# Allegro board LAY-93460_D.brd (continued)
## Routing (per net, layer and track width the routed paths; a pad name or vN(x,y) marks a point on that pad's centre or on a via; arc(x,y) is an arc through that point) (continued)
P3V3_BATT: length 17.4
  TOP w0.254: 38.67,43.76 D2.A ; D2.A 39.33,44.58 ; D2.A 38.67,45.41 ; D2.A 38.01,44.58
  BOTTOM w0.254: 37.33,38.87 BT2.1 ; BT2.1 35.31,40.58 ; BT2.1 37.33,42.3 ; BT2.1 39.35,40.58 ; v2(37.33,44.58) 39.3,44.58 ; v2(37.33,44.58) 37.33,46.09 ; v2(37.33,44.58) 37.33,43.07 ; v2(37.33,44.58) 35.36,44.58
  vias: v2(37.33,45.22) v2(37.33,43.95)
P3V3_LDO: length 1.8
  TOP w0.381: SH19.2 D1.C
P5V: length 79.5
  TOP w0.381: v2(21.64,49.4) D4.C 26.33,49.4 27.5,50.57 TP7.1 C23.1 v2(31.31,52.67)
  L4_INT_2 w0.381: v2(21.64,49.4) 20.48,48.24 20.48,41.71 v2(18.74,39.97) ; v2(31.31,52.67) 33.37,52.67 34.61,51.43 v2(34.61,49.67)
  BOTTOM w0.381: v2(21.64,49.4) 22.8,49.4 23.55,48.65 23.55,44.81 23.02,44.28 23.02,39.09 23.42,38.69 24.84,38.69 25.51,38.02 25.51,36.1 24.71,35.3 SH14.1 21.9,34.23 22.33,33.8 26.56,33.8 27.69,32.67 27.69,26.46 26.69,25.46 23.93,25.46 23.35,26.04 21.27,26.04 19.43,24.2 13.37,24.2 v2(12.79,24.78)
P5V_CAN: length 112.6
  TOP w0.254: U18.2 22.99,43.18 ; U18.2 20.34,43.18 ; U18.2 21.66,42.37 ; U18.2 21.66,43.99 ; v2(15.91,40.98) U17.1 ; 27.87,41.1 v2(27.87,43.18) ; v2(27.87,43.18) 27.87,45.26 ; v2(27.87,43.18) 26.54,43.18 ; v2(27.87,43.18) 29.19,43.18 ; U20.1 v2(15.91,44.03) ; U22.1 v2(13.29,28.23) ; U24.1 v2(16.34,28.23)
  L3_INT_1 w0.381: v2(10.21,29.64) 9.29,28.72 9.29,21.02 8.42,20.15 3.99,20.15 3.26,20.88 3.26,31.37 3.72,31.83 3.72,39.82 JS4.1 5.32,40.37 6.08,39.61 8.04,39.61 8.81,40.38 v2(13.66,40.38) 14.27,40.98 v2(15.91,40.98) 17.28,42.35 17.8,42.35 18.62,43.18 v2(27.87,43.18)
  L4_INT_2 w0.381: v2(21.64,52.45) 19.94,50.75 17.65,50.75 15.91,49.01 v2(15.91,44.03) v2(15.91,40.98)
  BOTTOM w0.381: JS4.1 6.03,40.73 C106.1 U19.5 ; U23.5 v2(10.21,29.64) 10.21,28.61 10.59,28.23 v2(13.29,28.23) v2(16.34,28.23) 19.12,28.23 19.57,28.68 19.57,30.53 19.18,30.91 v2(18.87,30.91) U23.3
P12V: length 26
  L4_INT_2 w0.381: J10.3 0.75,47.5 0.75,38.35 J11.3
  BOTTOM w0.254: J9.1 9.98,48.07 ; J9.1 10.92,46.13 ; J9.1 9.98,44.19 ; J9.1 9.04,46.13 ; 21.66,45.77 D8.A ; D8.A 20.84,46.6 ; D8.A 22.49,46.6 ; D8.A 21.66,47.43 ; 0.98,48.77 J10.3 ; J10.3 2.02,49.81 ; J10.3 3.06,48.77 ; J10.3 2.02,47.72
P12V_VBAT: length 2.9
  BOTTOM w0.508: D8.C C107.1 v2(21.66,40.88)
VBAT: length 10.5
  TOP w0.381: D2.C C25.1 41.72,47.64 42.43,48.34 42.43,49.36 43.18,50.11 45.85,50.11 46.23,50.49 JP2.1
VBAT_DCDC/VBAT_PMU: length 12.2
  TOP w0.254: L7.2 40.75,42.73 ; L7.2 41.46,42.15 ; L7.2 40.03,42.15 ; U6.51 42.17,35.77 ; U6.51 41.81,36.72 ; U6.51 41.81,34.83 ; 42.65,34 U6.50 ; C68.1 42.79,41.13 ; C68.1 C69.1 ; C68.1 42.13,40.35 ; C72.1 C69.1 ; C72.1 42.79,36.89 ; C72.1 42.13,37.68 ; C69.1 42.26,38.95 ; 42.65,33.5 U6.49
VBUS_USB: length 13.4
  TOP w0.381: J3.A4 J3.B9 4.36,27.78 3.98,27.4 3.98,23.91 4.36,23.53 J3.B4 J3.A9
  BOTTOM w0.305: J3.A9 7.26,23.53 7.77,23.02 L8.1 U9.6
VCC_IF_LINK: length 119.3
  TOP w0.254: U15.5 v1(32.47,39.69)
  TOP w0.381: SW4.1 54,3.8 v2(53.69,3.49) ; v1(49.61,1.46) 43.14,1.46 42.51,2.09 J5.1 C91.1 v2(40.73,4.8)
  L3_INT_1 w0.381: v2(68.93,3.49) 67.77,4.64 v1(66.25,4.64) 65.53,5.36 v2(63.37,5.36) 62.29,4.28 59.05,4.28 v2(58.26,3.49) v2(53.69,3.49)
  L4_INT_2 w0.381: JP18.2 46.23,41.79 44.22,39.78 v2(44.22,16.42) 44.22,8.44 42.77,7 40.62,7 40,6.39 40,5.53 v2(40.73,4.8)
  BOTTOM w0.254: v2(63.37,5.36) 63.9,5.36 ; v2(63.37,5.36) 62.83,5.36 ; v2(63.37,5.36) 63.37,5.89
  BOTTOM w0.381: JP18.2 44.7,50.11 37.61,50.11 36.04,48.54 32.12,48.54 31.39,47.81 31.39,40.08 31.78,39.69 v1(32.47,39.69) ; v1(66.25,4.64) U13.6 66.25,2.84 C90.1 ; v1(49.61,1.46) 49.61,1.46 49.65,1.49 49.65,2.09 50.03,2.47 C88.1 51.01,2.84 U12.6 51.01,4.22 51.26,4.47 53.43,4.47 53.69,4.22 v2(53.69,3.49) 54.2,3.49 C93.1 55.58,2.84 U14.6
VCC_TGMCU: length 73.3
  TOP w0.203: U16.10 v1(39.26,13.47) ; U16.1 35.35,11.18 v2(35.1,10.92) ; v2(40.15,10.21) U16.7 39.26,9.09 R101.1 ; U16.15 v1(36.76,13.47)
  TOP w0.381: R67.2 55.08,18.88 v2(55.45,18.51) ; JP18.1 47.33,47.69 v2(47.33,46.17)
  L3_INT_1 w0.305: v1(36.76,13.47) v1(39.26,13.47)
  L3_INT_1 w0.381: v1(39.48,18.85) 41.05,20.42 46.82,20.42 v2(47.62,21.22) 48.25,21.86 49.26,21.86 50.81,20.3 52.39,20.3 54.19,18.51 v2(55.45,18.51)
  L4_INT_2 w0.305: v1(36.76,13.47) 36.76,11.93 35.76,10.92 v2(35.1,10.92) ; v1(39.48,18.85) 39.48,13.68 v1(39.26,13.47) 39.26,11.1 v2(40.15,10.21)
  BOTTOM w0.203: v2(55.45,18.51) U11.14
  BOTTOM w0.381: v2(47.33,46.17) 48.07,46.17 49.22,45.03 49.22,41.54 47.62,39.94 v2(47.62,21.22)
VDD_ANA: length 10.4
  TOP w0.203: v2(64.84,24.64) 64.48,25 U1.29
  L4_INT_2 w0.381: v2(64.84,24.64) 64.84,22.07 JP9.2
VDD_CORE: length 45.3
  TOP w0.254: U1.16 58.91,20.77 C14.1 v2(58.14,18.99) ; U1.41 v1(60.91,30.05)
  TOP w0.381: TP1.1 64.16,36.72 63.48,36.05 v1(62.11,36.05)
  L4_INT_2 w0.305: v1(62.11,36.04) 61.42,35.36 61.42,32.71 60.4,31.69 59.43,31.69 58.63,30.9 58.63,23.26 58.94,22.95 58.94,21.27 58.14,20.48 v2(58.14,18.99)
  BOTTOM w0.381: TP1.1 68.81,34.96 67.03,33.17 65.56,33.17 64.85,32.46 64.85,31.03 64.23,30.41 63.28,30.41 62.9,30.03 C17.1 C16.1 v1(60.91,30.05)
VDD_DCDC: length 109.6
  TOP w0.254: 61.41,21.1 U1.21
  TOP w0.381: 61.41,21.1 63.38,19.13 63.38,18.22 63.03,17.86 C31.1 v2(64.17,17.48)
  L3_INT_1 w0.381: v2(56.76,51.18) 53.73,51.18 49.92,47.36 v1(32.45,47.36) ; v1(31.75,10.92) 34.21,10.92 34.9,10.23 38.56,10.23 39.28,10.94 62.32,10.94 v2(63.81,12.44)
  L4_INT_2 w0.381: v2(64.17,17.48) 64.17,12.8 v2(63.81,12.44) ; v1(31.75,10.92) 31.08,11.59 31.08,41.04 32.45,42.41 v1(32.45,47.36)
  BOTTOM w0.254: v2(64.17,17.48) SH22.2
VDD_IC: length 172.5
  TOP w0.381: SH21.1 JP2.3
  L3_INT_1 w0.381: v1(31.31,53.73) 39.29,53.73 41.39,51.64 JP2.2 ; v1(72.21,13.57) 68.59,13.57 67.86,12.84 67.86,10.47 65.69,8.3 43.48,8.3 42.68,7.5 36.25,7.5 33.82,9.93 31.77,9.93 31.14,10.57 31.14,12.14 30.7,12.57 v1(25.06,12.57)
  L4_INT_2 w0.381: v2(71.75,33.21) 71.75,34.58 72.15,34.98 72.15,46.98 69.43,49.7 69.43,51.99 67.08,54.35 46.94,54.35 JP2.3 JP2.2 ; v1(72.21,13.57) 72.36,13.57 73.22,14.42 73.22,17.19 72,18.41 v2(72,22.21) ; v1(31.31,53.73) 29.2,53.73 26.58,51.11 26.58,39.21 25.08,37.72 25.08,30.09 24.7,29.71 24.7,27.3 24.21,26.81 24.21,19.49 24.32,19.38 24.32,18.97 25.06,18.22 v1(25.06,12.57)
VDD_IO_ABC: length 11.8
  TOP w0.254: v1(55.47,27) U1.4
  TOP w0.381: C32.1 55.42,29.84 v2(55.13,29.56)
  L3_INT_1 w0.254: v1(55.47,27) 52.17,27 JP8.2
  L4_INT_2 w0.254: v1(55.47,27) 54.72,27 54.09,27.63 54.09,29.16 54.48,29.56 v2(55.13,29.56)
VDD_LDO_CORE: length 8.1
  TOP w0.254: U1.15 v1(58.41,21.47)
  BOTTOM w0.254: JP4.2 53.99,20.49 C37.1 C36.1 57.37,20.49 57.78,20.08 C35.1 v1(58.41,21.47)
VDD_MEM: length 19.6
  L3_INT_1 w0.381: v1(62.71,48.64) 61.67,49.68 57.03,49.68 56.05,48.7 JS1.1
  BOTTOM w0.381: v2(67.94,47.62) 66.6,47.62 65.91,46.94 R20.1 R10.1 R19.1 R11.1 v1(62.71,48.64)
VDD_PA_2G4: length 11
  TOP w0.254: L2.1 64.37,28.5 U1.36
  TOP w0.381: TP3.1 66.03,33.31 64.89,32.17 C7.1 C18.1 L2.1
  L4_INT_2 w0.254: v2(66.36,37.88) 66.03,37.55 TP3.1
VDD_REG: length 51.4
  L3_INT_1 w0.381: JP8.1 53.54,23.92 55.37,25.75 56.5,25.75 57.09,25.16 57.09,23.01 57.58,22.52 64.85,22.52 66.88,20.49 JP7.1
  BOTTOM w0.381: JP9.1 68.44,16.46 67.9,16.46 JP7.1 ; JP8.1 49.82,23.92 49.1,24.65 49.1,31.83 52.62,35.36 JP3.2 52.62,39.04 53,39.42 57.14,39.42 JP10.3
VDD_RF: length 21.5
  TOP w0.203: U1.34 64.67,27.5 64.84,27.33 v1(65.34,27.33)
  L4_INT_2 w0.305: v1(66.91,30.74) 66.91,33.04 67.4,33.52 67.4,39.73 v2(65.98,41.14)
  BOTTOM w0.254: v1(65.34,27.33) 65.3,27.33 64.77,27.85 63.66,27.85 C40.1 63.16,27.71 63.16,28.07 63.6,28.5 64.79,28.5 65.4,29.12 65.4,30.27 65.87,30.74 v1(66.91,30.74)
VDD_SWITCH: length 9.4
  TOP w0.254: v2(54.62,28.29) C26.1 54.62,26.33 54.95,26 U1.6
  BOTTOM w0.381: v2(54.62,28.29) 53.96,28.95 53.96,31.18 54.62,31.83 JP1.1
VOUT_SYS/VDD_SYS: length 3.9
  TOP w0.254: U1.22 v1(61.91,21.47)
  BOTTOM w0.254: C38.1 C39.1 61.65,20.31 61.76,20.42 C165.1 61.76,21.33 v1(61.91,21.47)
ADC0_A15: length 2.6
  TOP w0.203: U1.18 v1(59.91,21.47)
  BOTTOM w0.127: v1(59.91,21.47) U1.18 R8.1
ADC_IN: length 91
  L3_INT_1 w0.127: v1(61.4,36.55) 61.4,36.06 60.97,35.63 60.11,35.63 59.22,36.52 54.21,36.52 52.47,34.78 33.92,34.78 33.04,33.89 31.51,33.89 30.68,34.72 26.68,34.72 26.18,34.23 14.07,34.23 13.2,33.36 13.2,32.09 11.55,30.44 v1(7.66,30.44)
  L4_INT_2 w0.127: v1(5.65,18.11) 7.38,19.84 7.38,30.16 v1(7.66,30.44)
  BOTTOM w0.127: v1(61.4,36.55) 58.6,36.55 58.31,36.26 58.31,33.4 56.99,32.08 56.99,23.17 R8.2 ; v1(5.65,18.11) SH2.2
AN: length 1.9
  BOTTOM w0.127: SH2.1 J1.1
ANT: length 2.3
  TOP w0.417: U1.35 L2.2 L3.1
ANT_RF: length 2
  TOP w0.417: L3.2 C1.1 L10.1
BOOT_CFG: length 5.4
  TOP w0.203: SW4.2 50.55,3.8 50.3,4.06 50.3,6.45 C113.1 SH20.2
CAN0_RX: length 69.9
  TOP w0.198: v1(59.77,30.84) 59.98,30.63 59.98,29.94 59.91,29.87 U1.43
  L3_INT_1 w0.143: v1(59.77,30.84) 48.48,30.84 48.31,31.01 48.31,31.02 47.93,31.4 43.79,31.4 41.87,29.48 27.38,29.48 26.65,28.75 25.66,28.75 v1(25.39,28.48) ; v2(18.74,38.96) 19.32,39.53 19.32,40.3 19.45,40.43 20.16,40.43 21.63,41.9 27.96,41.9 28.5,42.44 29.62,42.44 30.15,42.98 30.15,43.32 30.33,43.5 30.36,43.5 v1(30.43,43.57)
  L4_INT_2 w0.143: v1(30.43,43.57) 30.14,43.85 29.54,43.85 29.03,43.34 29.03,41.36 28.32,40.65 28.32,39.32 26.02,37.02 26.02,29.11 v1(25.39,28.48)
CAN0_TX: length 70.7
  TOP w0.198: v1(60.54,30.84) 60.33,30.63 60.33,29.94 60.41,29.87 U1.42
  L3_INT_1 w0.143: v1(30.43,44.5) 29.8,43.86 29.8,43.12 29.47,42.8 28.35,42.8 27.81,42.25 21.49,42.25 20.01,40.78 19.45,40.78 19.35,40.88 19.35,41.39 v2(18.74,42) ; v1(60.54,30.84) 60.01,31.37 59.51,31.37 59.34,31.2 48.63,31.2 48.07,31.76 48.07,31.76 47.96,31.76 47.95,31.76 43.75,31.76 43.75,31.76 43.64,31.76 43.53,31.65 43.53,31.65 41.72,29.83 27.23,29.83 26.5,29.1 25.69,29.1 v1(25.39,29.41)
  L4_INT_2 w0.143: v1(25.39,29.41) 25.66,29.68 25.66,37.17 27.97,39.47 27.97,40.8 28.68,41.51 28.68,43.49 29.39,44.21 30.14,44.21 v1(30.43,44.5)
CAN1_RX: length 14.1
  TOP w0.203: R117.2 12.9,23.65 19.13,23.65 JP27.3
CAN1_TX: length 9.1
  TOP w0.203: JP28.3 20.89,26.17 18.82,24.1 15.5,24.1 R120.2
CAN_DIR: length 24.2
  TOP w0.203: v2(17.72,39.97) U17.5
  TOP w0.254: U22.5 v2(12.79,25.79)
  L3_INT_1 w0.127: v1(12.14,39.11) 12.6,39.57 14.08,39.57 14.74,40.22 15.61,40.22 15.86,39.97 v2(17.72,39.97)
  L4_INT_2 w0.127: v2(12.79,25.79) 12.37,26.21 12.37,30.67 13.75,32.05 13.75,35.59 14.54,36.37 14.54,37.88 13.31,39.11 v1(12.14,39.11)
CAN_HI_1: length 19.5
  TOP w0.198: R99.2 7.63,42.03 v1(6.99,41.39)
  L4_INT_2 w0.143: v1(6.99,41.39) 8.23,42.63 8.23,47.96 7.05,49.14 5.47,49.14 4.12,50.49 4.12,51.73 3.1,52.75 2.16,52.75 2.02,52.9 J10.1
  BOTTOM w0.198: U19.7 7.25,41.65 v1(6.99,41.39)
CAN_HI_2: length 22.4
  TOP w0.198: v1(10.22,31.93) 10.67,31.93 R118.2
  L4_INT_2 w0.143: J11.1 2.02,41.21 2.16,41.07 3.98,41.07 5.49,39.56 8.84,39.56 9.65,38.74 9.65,35.98 9.98,35.65 10.99,35.65 11.9,34.73 11.9,32.65 11.18,31.93 v1(10.22,31.93)
  BOTTOM w0.198: v1(10.22,31.93) 10.47,32.18 U23.7
CAN_LO_1: length 20.1
  TOP w0.198: v1(6.99,40.63) 7.63,39.99 R45.1
  L4_INT_2 w0.143: J10.2 2.02,52.25 2.16,52.4 2.95,52.4 3.76,51.58 3.76,50.35 5.32,48.79 6.9,48.79 7.87,47.81 7.87,42.8 6.9,41.82 6.77,41.82 6.48,41.53 6.48,41.14 v1(6.99,40.63)
  BOTTOM w0.198: U19.6 7.25,40.38 v1(6.99,40.63)
CAN_LO_2: length 22.9
  TOP w0.198: R119.1 10.67,31.17 v1(10.21,31.17)
  L4_INT_2 w0.143: J11.2 2.02,40.57 2.16,40.71 3.83,40.71 5.35,39.2 8.69,39.2 9.29,38.6 9.29,35.83 9.83,35.29 10.84,35.29 11.55,34.58 11.55,32.8 11.03,32.28 10.47,32.28 10.4,32.36 10.04,32.36 9.79,32.11 9.79,31.58 v1(10.21,31.17)
  BOTTOM w0.198: U23.6 10.46,30.91 v1(10.21,31.17)
CAN_RX_1: length 2.4
  TOP w0.198: U17.3 v1(15.07,39.47)
  BOTTOM w0.198: U19.4 14.7,39.11 v1(15.07,39.47)
CAN_RX_2: length 14.9
  TOP w0.198: v1(11.78,27.54) U22.3
  L3_INT_1 w0.143: v1(11.78,27.54) 12.4,26.93 14.86,26.93 15.26,27.32 15.26,27.47 15.26,27.47 15.26,28.07 14.31,29.01 14.31,30.23 14.69,30.6 16.55,30.6 17.04,31.09 17.77,31.09 18.1,30.76 18.1,30.41 v1(18.87,29.64)
  BOTTOM w0.198: v1(18.87,29.64) U23.4
CAN_TX_1: length 2.5
  TOP w0.198: U20.3 v1(15.06,42.52)
  BOTTOM w0.198: U19.1 14.66,42.92 v1(15.06,42.52)
CAN_TX_2: length 11.6
  TOP w0.198: v1(14.83,27.54) U24.3
  L3_INT_1 w0.143: v1(18.87,32.84) 18.1,32.08 18.1,31.81 17.73,31.45 16.89,31.45 16.4,30.96 14.54,30.96 13.96,30.38 13.96,28.87 14.83,27.99 v1(14.83,27.54)
  BOTTOM w0.198: v1(18.87,32.84) 18.26,33.45 U23.1
CS: length 13.4
  TOP w0.203: TP11.1 70.26,48.89 69.75,49.4 65.81,49.4 64.03,47.62 v2(60.68,47.62)
  BOTTOM w0.203: R21.2 v2(60.68,47.62) R11.2
DBGIF_DETECT: length 1.4
  TOP w0.203: U6.78 R81.1
DBGIF_ISP0_CTRL: length 4.4
  TOP w0.203: U6.72 31.31,37.29 32.22,38.2 32.22,38.72 31.91,39.04 U15.2
DBGIF_RESET: length 49.7
  TOP w0.254: U6.90 v1(29.39,27)
  L3_INT_1 w0.127: v1(28.47,11.81) 28.51,11.76 30.22,11.76 30.56,11.42 30.56,10.33 33.81,7.07 42.86,7.07 43.66,7.87 55.81,7.87 v1(56.88,6.8)
  L4_INT_2 w0.127: v1(28.47,11.81) 28.47,14.93 29.39,15.86 v1(29.39,27)
  BOTTOM w0.203: U14.3 v1(56.88,6.8)
DBGIF_RESET_TXEN: length 59.7
  TOP w0.203: U6.71 v1(31.81,34.54)
  L3_INT_1 w0.127: v2(56.23,2.47) 49.36,2.47 48.58,1.69 40.71,1.69 40.26,2.14 35.37,2.14 34.63,1.39 v1(33.7,1.39)
  L4_INT_2 w0.127: v1(33.7,1.39) 33.7,8.2 32.93,8.96 32.93,11.14 32.3,11.77 32.3,34.05 v1(31.81,34.54)
  BOTTOM w0.203: U14.5 v2(56.23,2.47)
DBGIF_TCK_SWCLK: length 65.6
  TOP w0.203: v1(41.29,37.03) 40.65,37.03 40.31,36.69 U6.54
  L3_INT_1 w0.127: v1(61.72,1.04) 61.05,1.71 59.12,1.71 58.4,0.99 40.3,0.99 v1(39.9,1.39)
  L4_INT_2 w0.127: v1(39.9,1.39) 39.9,4.68 39.5,5.08 39.5,6.88 40.19,7.58 42.22,7.58 43.58,8.94 43.58,34.74 v1(41.29,37.03)
  BOTTOM w0.203: U10.2 v1(61.72,1.04)
DBGIF_TDI: length 47.5
  TOP w0.203: v1(33.77,18.54) 33.77,18.84 33.57,19.05 33.01,19.05 32.81,19.25 U6.7
  L3_INT_1 w0.127: v1(35.68,1.39) 36.4,0.68 58.88,0.68 59.23,1.04 v1(60.91,1.04)
  L4_INT_2 w0.127: v1(33.77,18.54) 33.77,10.08 35.11,8.74 35.11,6.57 35.68,6 v1(35.68,1.39)
  BOTTOM w0.203: v1(60.91,1.04) 61.22,1.35 U10.3
DBGIF_TDO_SWO: length 55.5
  TOP w0.203: v1(30.19,31) 29.69,30.5 U6.83
  L3_INT_1 w0.127: v1(29.56,10.79) 29.56,5.81 30.16,5.21 32.96,5.21 34.52,6.77 42.98,6.77 43.78,7.57 51.16,7.57 v1(53.23,5.5)
  L4_INT_2 w0.127: v1(30.19,31) 30.19,29.79 30.47,29.51 30.47,14.88 29.56,13.97 v1(29.56,10.79)
  BOTTOM w0.203: v1(53.23,5.5) 52.8,5.06 52.51,5.06 52.31,5.27 U12.3
DBGIF_TMS_SWDIO: length 67.4
  TOP w0.203: U6.81 28.88,31.5 v1(29.38,31)
  L3_INT_1 w0.127: v1(29.43,14.7) 29.96,14.17 35.72,14.17 36.29,14.73 45.19,14.73 46.33,13.6 52.18,13.6 53.8,11.98 61.96,11.98 64.07,14.09 v1(67.55,14.09)
  L4_INT_2 w0.127: v1(67.55,14.09) v1(67.55,6.93) ; v1(29.43,14.7) 30.17,15.44 30.17,29.3 29.38,30.08 v1(29.38,31)
  BOTTOM w0.203: v1(67.55,6.93) U13.3
DBGIF_TMS_SWDIO_TXEN: length 67.9
  TOP w0.203: v1(37.84,34.18) 37.48,34.54 34.6,34.54 34.31,34.83 U6.66
  L3_INT_1 w0.127: v1(38.53,14.14) 45.3,14.14 46.15,13.29 51.93,13.29 53.55,11.67 62.08,11.67 63.87,13.45 v1(66.9,13.45)
  L4_INT_2 w0.127: v1(66.9,13.45) v2(66.9,2.47) ; v1(37.84,34.18) 39.28,32.75 39.28,21.1 38.53,20.35 v1(38.53,14.14)
  BOTTOM w0.203: U13.5 v2(66.9,2.47)
DBGIF_VREF: length 5.3
  TOP w0.254: R43.2 R44.1 C82.1 41.42,18.49 40.81,19.1 U6.23
DCDC_LX: length 1.8
  TOP w0.279: U1.20 60.91,20.51
EXTAL32K: length 5.7
  TOP w0.127: R31.1 65.95,21.5 65.95,23.24 65.06,24.13 64.52,24.13 64.15,24.5 U1.28
EXTAL32K_PTD5: length 3.1
  TOP w0.127: R31.2 68.2,20.71 68.52,21.03 Y2.2 C50.1
EXTAL_32M: length 0.9
  TOP w0.203: Y1.3 R32.1
EXTAL_RF: length 5.4
  TOP w0.127: v1(64.41,27) U1.33
  L3_INT_1 w0.127: v1(64.41,27) 65.19,26.21 67,26.21 67.94,25.28 v2(67.94,24.92)
FL_USB1_DM: length 40.9
  TOP w0.228: U6.35 42.49,26.5 v1(42.17,26.82) ; R39.2 9.07,25.47 9.95,25.47 v1(10.24,25.19)
  BOTTOM w0.228: v1(42.17,26.82) 42.17,26.58 42.04,26.45 42.04,25.98 41.77,25.72 32.7,25.72 27.99,21.01 20.16,21.01 18.12,23.05 12.24,23.05 11.4,23.89 11.4,25.25 11.18,25.47 10.53,25.47 v1(10.24,25.19)
FL_USB1_DP: length 41.4
  TOP w0.228: U6.34 41.94,26 41.56,26.39 v1(41.56,26.82) ; v1(10.24,26.12) 9.95,25.83 9.07,25.83 R40.2
  BOTTOM w0.228: v1(10.24,26.12) 10.53,25.83 11.32,25.83 11.75,25.4 11.75,24.04 12.39,23.4 18.27,23.4 20.31,21.36 27.84,21.36 32.55,26.07 41.63,26.07 41.68,26.13 41.68,26.45 41.56,26.58 v1(41.56,26.82)
FL_USB_5V0: length 120.1
  TOP w0.381: v2(12.27,19.21) C76.1 C75.1 v2(10.24,23.02)
  L3_INT_1 w0.381: v1(48.23,50.11) 39.92,50.11 38.88,51.16 29.81,51.16 28.52,52.45 v2(23.8,52.45) 22.12,50.77 21.36,50.77 20.34,49.75 7.75,49.75 5.32,47.31 JS4.2 ; v2(12.27,19.21) 5.34,19.21 4.32,18.19 v1(3.26,18.19)
  L4_INT_2 w0.381: v2(46.22,30) 46.22,40.52 48.49,42.79 48.49,46.75 49.27,47.53 49.27,49.07 v1(48.23,50.11)
  BOTTOM w0.381: JS4.2 4.06,43.43 3.52,42.89 3.52,31.63 3.26,31.37 3.26,28.15 2.23,27.12 2.23,23.33 3.26,22.3 v1(3.26,18.19) ; v2(12.27,19.21) 12.27,21.26 13.28,22.27 v2(15.27,22.27)
GPO0: length 97
  TOP w0.203: U1.13 v1(57.41,21.47)
  L3_INT_1 w0.127: v1(59.41,34.17) 60.35,35.11 62.32,35.11 63.58,36.37 63.58,38.29 62.64,39.23 48.69,39.23 46.07,36.61 45.1,36.61 44.34,35.85 v1(27.34,35.85)
  L4_INT_2 w0.127: v1(57.41,21.47) 57.41,22.46 57.01,22.86 57.01,31.13 59.41,33.52 v1(59.41,34.17) ; J12.1 30.7,4.77 31.89,5.97 31.89,9.09 31.44,9.55 28.42,9.55 27.56,10.41 27.56,15.21 28.54,16.19 28.54,28.89 27.62,29.8 27.62,35.57 v1(27.34,35.85)
GPO1: length 97.9
  TOP w0.203: U1.14 v1(57.91,21.07)
  L3_INT_1 w0.127: v1(60.41,34.17) 60.95,34.71 62.41,34.71 63.88,36.18 63.88,38.42 62.77,39.53 48.65,39.53 45.97,36.85 45,36.85 44.31,36.16 28.96,36.16 28.79,36.32 v1(28,36.32)
  L4_INT_2 w0.127: v1(60.41,34.17) 60.41,33.31 59.78,32.69 59.1,32.69 57.42,31.01 57.42,23.06 57.91,22.57 v1(57.91,21.07) ; v1(28,36.32) 28,29.95 28.92,29.02 28.92,16.06 27.93,15.06 27.93,10.75 28.75,9.94 31.82,9.94 32.32,9.43 32.32,5.88 32.7,5.5 J12.2
GPO2: length 111.7
  TOP w0.203: U1.17 v1(59.41,21.07)
  L3_INT_1 w0.127: JP23.3 6.84,7.19 11.53,7.19 v1(12.69,8.35) ; v1(62.51,34.17) 64.19,35.84 64.19,38.55 62.89,39.84 48.53,39.84 45.79,37.09 44.9,37.09 44.27,36.46 29.48,36.46 29.17,36.78 27.37,36.78 25.78,35.19 18.53,35.19 17.48,36.24 14.21,36.24 v1(13.27,35.3)
  L4_INT_2 w0.127: v1(12.69,8.35) 12.69,10.27 12.02,10.94 12.02,14.92 11.58,15.37 11.58,15.39 11.11,15.86 11.11,30.53 13.27,32.69 v1(13.27,35.3) ; v1(62.51,34.17) 61.91,33.56 61.91,30.7 61.43,30.22 61.43,29.79 59.65,28.01 59.65,21.88 59.41,21.64 v1(59.41,21.07)
H/RST: length 1
  BOTTOM w0.203: v2(67.94,46.35) R20.2
HW_VER_1: length 3.1
  TOP w0.203: U6.73 30.81,37.48 R102.1
HW_VER_2: length 4
  TOP w0.203: U6.65 34.81,37.33 35.27,37.79 36.22,37.79 R104.1
HW_VER_3: length 2.1
  TOP w0.203: U6.1 29.81,19.02 29.55,18.76 R105.1
HW_VER_4: length 6.6
  TOP w0.203: R106.1 43,21.25 42.53,21.71 42.53,24.3 42.74,24.5 U6.31
HW_VER_6: length 41
  TOP w0.203: U6.56 v1(39.31,36.95)
  L4_INT_2 w0.127: JP21.2 41.84,43.25 39.31,40.72 v1(39.31,36.95) 39.31,34.74 41.65,32.4 41.65,29.35 40.88,28.58 40.88,24.91 41.65,24.14 v1(41.65,11.68)
  BOTTOM w0.127: v1(41.65,11.68) 41.65,12.52 42.16,13.03 Q3.1
HW_VER_7: length 44.2
  TOP w0.127: U6.27 v1(44.8,22.5)
  TOP w0.203: v1(59.28,3.49) JP22.2
  L3_INT_1 w0.127: v1(63.92,21.18) 63.35,20.61 55.7,20.61 53.4,22.91 45.21,22.91 v1(44.8,22.5)
  L4_INT_2 w0.127: JP22.2 59.28,11.78 63.16,15.66 63.16,20.42 v1(63.92,21.18)
  BOTTOM w0.203: v1(59.28,3.49) 59.97,3.49 60.72,4.24 U10.5
HW_VER_8: length 3.7
  TOP w0.203: U6.55 39.81,36.83 40.75,37.76 R96.1
I2C1_SCL: length 67.8
  TOP w0.203: U1.3 v1(55.88,27.5)
  L3_INT_1 w0.127: v1(57.24,37.88) 56.48,37.12 53.84,37.12 52.1,35.38 26.66,35.38 26.12,34.84 15.26,34.84 v2(14.79,35.3)
  L4_INT_2 w0.127: v1(55.88,27.5) 56.61,28.23 56.61,31.49 58.4,33.28 58.4,35.38 57.26,36.52 57.26,37.86 v1(57.24,37.88) 57.24,39.44 57.74,39.94 57.74,43.48 58.14,43.88 v1(58.14,44.57)
  BOTTOM w0.127: R206.2 54.66,26.98 55.17,27.5 v1(55.88,27.5)
  BOTTOM w0.203: R15.1 58.65,45.08 v1(58.14,44.57)
I2C1_SDA: length 106.7
  TOP w0.203: U1.2 v1(55.47,28)
  L3_INT_1 w0.127: v1(17.33,26.29) 20.4,26.29 22.16,24.52 25.42,24.52 26.31,25.41 47.99,25.41 50.14,27.56 55.04,27.56 v1(55.47,28) ; JP24.3 7.42,12.95 v1(14.54,12.95) ; v1(57.63,48.64) 61.5,48.64 63.15,46.99 69.34,46.99 v1(69.98,46.35)
  L4_INT_2 w0.127: v1(14.54,12.95) 14.54,15.37 16.25,17.08 16.25,19.86 16.87,20.48 16.87,25.83 v1(17.33,26.29) ; v1(55.47,28) 56.2,28.73 56.2,31.53 57.99,33.31 57.99,35.24 56.57,36.65 56.57,39.38 57.37,40.18 57.37,43.79 57.63,44.05 v1(57.63,48.64)
  BOTTOM w0.127: v1(55.47,28) 55.12,28 54.75,27.63 54.12,27.63 R205.2
  BOTTOM w0.203: R21.1 v1(57.63,48.64) ; R18.1 v1(69.98,46.35)
I2C_SCL: length 1.8
  BOTTOM w0.127: J2.5 SH11.2
I2C_SDA: length 1.8
  BOTTOM w0.127: J2.6 SH13.2
IF_DETECT: length 57.9
  TOP w0.203: R81.2 27.14,34.54 29.14,34.54 29.34,34.34 v1(29.34,34)
  L3_INT_1 w0.127: v1(28.92,10.54) 28.92,5.81 29.83,4.9 38.69,4.9 41.17,2.43 47.93,2.43 v2(49.04,3.53)
  L4_INT_2 w0.127: v1(29.34,34) 28.87,33.53 28.87,30.13 29.86,29.15 29.86,15.82 28.92,14.88 v1(28.92,10.54)
  BOTTOM w0.203: v2(49.04,3.53) J5.9 D14.C
IF_ISPEN: length 46.6
  L3_INT_1 w0.127: v1(42.16,9.29) v1(46.96,9.29)
  L4_INT_2 w0.127: v1(42.16,9.29) 42.16,10.51 41.21,11.45 41.21,24.07 40.5,24.79 40.5,28.72 41.21,29.44 41.21,32.37 36.77,36.82 36.77,37.42 36.11,38.09 36.11,38.09 v2(35.81,38.39) ; J5.7 46.96,4.17 v1(46.96,9.29)
  BOTTOM w0.203: J5.7 46.32,2.73 45.97,2.38 44.65,2.38 44.45,2.18 D13.C
IF_TCK_SWDCLK: length 34.7
  L3_INT_1 w0.127: v2(43.78,6.33) 49.81,6.33 51.55,4.59 56.23,4.59 57.29,5.66 v2(58.26,5.66)
  BOTTOM w0.203: J5.4 v2(43.78,6.33) 43.78,7.34 47.08,10.63 47.08,14.8 47.28,15.01 D15.5 48.89,15.01 50.02,16.13 52.62,16.13 53.01,16.53 U11.3
IF_TDI: length 25.6
  TOP w0.203: v1(46.46,15.66) 45.64,14.85 45.64,11.31 46.32,10.63 J5.8
  L3_INT_1 w0.127: J5.8 47.24,5.72 49.38,5.72 51.15,3.95 57.56,3.95 v2(58.26,4.64)
  BOTTOM w0.203: D15.3 v1(46.46,15.66)
IF_TDO_SWO: length 37.7
  TOP w0.203: J5.6 45.05,10.44 44.83,10.66 44.83,15.06 45.64,15.87 v1(45.64,16.42)
  L4_INT_2 w0.127: J5.6 44.43,4.18 44.43,2.45 45.41,1.47 48.94,1.47 49.44,1.98 52.15,1.98 v2(52.67,1.46)
  BOTTOM w0.203: U11.11 53.41,19.53 52.8,20.14 46.75,20.14 45.64,19.03 v1(45.64,16.42) 45.66,16.4 46.57,16.4 47.32,15.66 D15.4
IF_TMS_SWDIO: length 73.1
  TOP w0.203: J5.2 41.5,5.82 v2(40.73,5.82)
  L3_INT_1 w0.127: v1(48.63,14.36) 49.08,13.9 52.44,13.9 53.81,12.52 v1(61.29,12.52) ; v1(68.31,5.83) 62.72,5.83 61.98,5.09 57.97,5.09 57.16,4.28 51.35,4.28 49.6,6.02 44.81,6.02 44.61,5.82 v2(40.73,5.82)
  L4_INT_2 w0.127: v1(48.63,14.36) 45.29,11.02 45.29,8.61 43.02,6.34 41.25,6.34 v2(40.73,5.82) ; v2(67.91,1.46) 67.91,3.99 68.31,4.39 v1(68.31,5.83)
  BOTTOM w0.203: D15.6 v1(48.63,14.36) ; U11.15 55.01,18.11 56.08,17.04 58.6,17.04 61.29,14.36 v1(61.29,12.52)
IF_TRGRST_SWDRST: length 34.6
  TOP w0.203: J5.10 47.59,10.68 46.46,11.81 v1(46.46,14.36)
  L3_INT_1 w0.127: J5.10 49.69,4.8 51.56,2.93 56.71,2.93 57.24,2.39 v2(57.24,1.46) ; v1(50.15,19.61) 49.13,18.59 47.43,18.59 v1(46.91,19.11)
  L4_INT_2 w0.127: v1(46.91,19.11) 47.75,18.27 47.75,15.66 v1(46.46,14.36)
  BOTTOM w0.127: U11.7 51.48,18.51 50.56,18.51 50.15,18.92 v1(50.15,19.61)
  BOTTOM w0.203: v1(46.46,14.36) D15.1
L_B4: length 1.3
  TOP w0.203: R22.2 LED4.C
L_G2: length 1.3
  TOP w0.203: R23.1 LED2.C
LED1_B1: length 4.4
  TOP w0.203: JS14.2 29.1,6.33 28.42,5.65 R28.2 Q1.1
LED2_G: length 2.5
  TOP w0.203: Q2.3 R23.2
LED2_G2: length 2.3
  TOP w0.203: Q2.1 R29.2 R27.1
LED4_B: length 2.9
  TOP w0.203: Q1.3 R22.1
LED_RTS: length 1.8
  TOP w0.203: R24.2 JS3.2
LLWU/NMI_B: length 7.6
  BOTTOM w0.203: SH5.2 12,35.94 12,38.19 11.73,38.46 9.57,38.46 J2.2
LPSPI_PCS0: length 86.4
  TOP w0.203: v1(58.91,36.05) 58.41,35.55 U1.46
  L3_INT_1 w0.127: v1(14.64,33.66) 14.91,33.92 26.65,33.92 27.04,33.53 33.18,33.53 34.14,34.49 36.91,34.49 37.7,33.7 41.38,33.7 42.15,34.47 52.74,34.47 54.26,35.99 55.23,35.99 55.63,35.6 58.46,35.6 v1(58.91,36.05)
  L4_INT_2 w0.127: v1(14.64,33.66) 14.16,33.17 14.16,31.92 12.68,30.45 12.68,26.99 13.3,26.37 13.3,18.65 v1(11.74,17.09) ; v1(58.65,47.62) 58.14,47.11 58.14,45.43 58.65,44.92 58.65,40.2 59.39,39.46 59.39,36.53 v1(58.91,36.05)
  BOTTOM w0.127: SH4.2 v1(11.74,17.09)
  BOTTOM w0.203: v1(58.65,47.62) R16.1
LPSPI_SCK: length 88.8
  TOP w0.203: U1.48 v1(57.41,34.17)
  L3_INT_1 w0.127: v1(64.17,34.17) 63.47,34.17 63,33.7 57.88,33.7 v1(57.41,34.17) 42.45,34.17 41.68,33.4 37.55,33.4 36.76,34.19 34.35,34.19 33.36,33.2 26.91,33.2 26.5,33.62 15.59,33.62 v1(15.28,33.3)
  L4_INT_2 w0.127: v1(14.28,17.09) 14.28,26.53 13.91,26.9 13.91,30.48 14.83,31.4 14.83,32.86 15.27,33.3 v1(15.28,33.3)
  BOTTOM w0.127: v1(14.28,17.09) SH6.2
  BOTTOM w0.203: v1(64.17,34.17) 64.17,35.95 65.25,37.03 65.25,38.42 65.69,38.86 67.56,38.86 69.96,41.26 69.96,44.76 69.63,45.08 R12.1
LPSPI_SIN: length 72.2
  TOP w0.203: U1.47 v1(57.91,30.05)
  L3_INT_1 w0.127: v1(16.82,16.58) 19.6,16.58 24.35,21.33 v1(31.75,21.33) ; v1(57.91,30.05) 50.12,30.05 47.11,27.05 43.37,27.05 42.94,27.47 32.23,27.47 v1(31.75,26.98)
  L4_INT_2 w0.127: v1(31.75,21.33) v1(31.75,26.98) ; v1(57.91,30.05) 57.91,30.84 59.35,32.29 60.03,32.29 60.88,33.14 60.88,34.64 59.68,35.84 59.68,39.58 59.03,40.23 59.03,45.97 v1(58.65,46.35)
  BOTTOM w0.127: SH8.2 16.31,17.09 v1(16.82,16.58)
  BOTTOM w0.203: R13.1 v1(58.65,46.35)
LPSPI_SOUT: length 92.4
  TOP w0.203: U1.1 56.14,28.5 55.97,28.67 55.97,29.14 56.91,30.08 v1(56.91,33.4)
  L3_INT_1 w0.127: v1(15.91,32.94) 16.28,33.31 26.37,33.31 26.84,32.84 33.64,32.84 34.68,33.88 36.63,33.88 37.47,33.04 41.97,33.04 42.79,33.86 55.48,33.86 55.93,33.4 v1(56.91,33.4) v1(63.45,33.4)
  L4_INT_2 w0.127: v1(14.28,16.19) 14.75,16.67 14.75,26.7 14.27,27.18 14.27,30.29 15.3,31.31 15.3,32.33 v1(15.91,32.94)
  BOTTOM w0.127: SH10.2 18.35,17.53 18.22,17.66 15.16,17.66 14.9,17.4 14.9,16.43 14.66,16.19 v1(14.28,16.19)
  BOTTOM w0.203: v1(63.45,33.4) 63.45,36.24 64.44,37.23 64.44,38.83 65.14,39.52 66.87,39.52 68.96,41.61 R14.1
MCU_LINK_3V3: length 84.4
  TOP w0.254: 20.54,20.84 L4.2 21.11,20.12 ; U6.84 27.11,30 v2(26.61,30.5) ; U6.95 v2(26.61,24.5) ; v2(26.61,23.52) 26.64,23.54 26.64,23.61 27.03,24 U6.96 ; v2(45.08,30.74) 44.82,31 U6.44 ; v2(32.81,37.21) U6.69 ; 25.61,20.84 C51.1 24.82,20.17 ; v2(35.81,37.21) U6.63 ; U6.75 v2(29.81,37.21) ; U6.15 36.81,19.43 36.28,18.89 34.99,18.89 34.54,18.44 v2(34.54,17.78) ; 23.04,20.17 C54.1 ; U6.38 44.77,28 v2(45.08,27.69)
  TOP w0.381: L4.2 C54.1 C51.1
  L3_INT_1 w0.381: v1(26.61,17.78) v2(34.54,17.78) 43.17,17.78 v2(45.2,19.81) ; v2(29.81,37.21) v2(32.81,37.21) 33.07,37.21 33.11,37.17 33.56,37.17 33.6,37.21 v2(35.81,37.21)
  L4_INT_2 w0.381: v2(45.2,19.81) 45.89,20.49 45.89,23.92 45.08,24.73 v2(45.08,27.69) ; v1(26.61,17.78) v2(26.61,23.52) v2(26.61,24.5) 25.72,25.39 25.72,27.57 26.61,28.46 v2(26.61,30.5) 26.61,36.33 27.49,37.21 v2(29.81,37.21)
  BOTTOM w0.381: v2(45.08,30.74) 44.68,30.74 44.3,30.36 44.3,28.08 44.68,27.69 v2(45.08,27.69)
MCU_LINK_N_16MHZ: length 6.1
  TOP w0.203: U6.28 45.07,23 45.96,23.89 Y4.1 C78.1
MCU_LINK_P_16MHZ: length 7.3
  TOP w0.203: U6.29 44.78,23.5 45.48,24.2 45.48,25.33 46.04,25.89 Y4.2 C77.1
MCU_LINK_RST: length 58
  TOP w0.203: v1(42.07,22.5) 42.07,24.32 42.32,24.58 42.33,24.58 42.6,24.84 42.6,24.85 42.75,25 U6.32
  L3_INT_1 w0.127: J4.10 11.04,1.99 22.87,1.99 23.62,1.23 v1(23.62,1.23) ; v1(42.07,22.5) 40.31,22.5 38.26,20.44 25.86,20.44 v1(23.21,17.79)
  L4_INT_2 w0.127: v1(23.21,17.79) 23.21,16.96 24.33,15.84 24.33,8.75 21.94,6.36 21.94,3.88 23.62,2.2 v1(23.62,1.23)
MCU_LINK_USB_CC1: length 1.9
  TOP w0.381: J3.A5 6.99,26.93 R112.1
MCU_LINK_USB_CC2: length 1.2
  BOTTOM w0.305: J3.B5 R113.1
MCU_LINK_USB_DN: length 4.6
  TOP w0.203: R39.1 7.17,25.1 7.04,25.23 J3.A7
  BOTTOM w0.127: J3.A7 6.64,25.23 6.81,25.4 U9.1
  BOTTOM w0.203: J3.A7 5.62,25.71 5.12,25.71 J3.B7
MCU_LINK_USB_DP: length 4.6
  TOP w0.203: R40.1 7.17,26.2 7.04,26.08 J3.A6 5.62,25.59 5.12,25.59 J3.B6
  BOTTOM w0.127: J3.A6 6.64,26.08 6.81,25.9 U9.2
MCU_LNK_RX: length 27
  TOP w0.203: v1(36.39,33.41) 35.64,34.16 32.81,34.16 32.31,34.66 U6.70 ; v1(37.76,14.14) U16.13
  L4_INT_2 w0.127: v1(37.76,14.14) 37.76,20.24 37.33,20.67 37.33,32.47 v1(36.39,33.41)
MCU_LNK_TX: length 28.7
  TOP w0.203: U16.14 37.26,13.64 v1(36.76,14.14) ; v1(35.32,32.86) 32.86,32.86 32.5,32.5 U6.79
  L4_INT_2 w0.127: v1(35.32,32.86) 35.73,32.86 36.31,32.28 36.31,14.59 v1(36.76,14.14)
MCULINK_VDDA: length 6.6
  TOP w0.254: U6.16 C64.1 C63.1 37.31,15.66 37.44,15.54 R33.1 L5.2
MLINK_3V3: length 177.4
  TOP w0.203: U16.16 35.35,11.68 v2(35.1,11.93)
  TOP w0.254: R50.1 v1(22.74,1.23)
  TOP w0.381: v2(21.11,22.53) C53.1 R34.2 ; v2(14.73,6.05) 9.01,6.05 v2(8.25,5.29) 8.25,1.95 8.97,1.23 v1(11.17,1.23) v1(15.74,1.23) ; v2(29.8,39.5) 29.8,40.19 31.77,42.15 L7.1
  L3_INT_1 w0.381: v1(51.01,12.52) 42.83,12.52 42.39,12.96 40.29,12.96 39.26,11.93 v2(35.1,11.93) 33.69,13.34 24.74,13.34 23.33,11.93 v1(22.19,11.93) ; v2(29.8,39.5) 27.64,37.34 27.07,37.34 25.43,35.69 19.62,35.69 v1(19.62,35.68) ; v2(66.25,6.93) 67.62,8.31 72.43,8.31 73.91,9.78 v2(73.91,19.67) ; v1(22.74,1.23) v1(15.74,1.23)
  L4_INT_2 w0.305: v2(34.5,14.96) 35.1,14.36 v2(35.1,11.93)
  L4_INT_2 w0.381: v1(22.74,1.23) R50.1 21.49,3.24 21.49,8.98 22.19,9.68 v1(22.19,11.93) 22.19,20.1 21.11,21.18 v2(21.11,22.53) 21.11,25.8 19.62,27.3 v1(19.62,35.68) ; v2(66.25,6.93) 65.23,5.91 65.23,4.22 v2(63.37,2.36) ; v2(51.01,6.93) v1(51.01,12.52)
  BOTTOM w0.254: R46.1 v1(11.17,1.23) ; v2(63.37,2.36) 63.9,2.36 ; v2(63.37,2.36) 62.83,2.36 ; v2(63.37,2.36) 63.37,1.82 ; R47.1 v1(15.74,1.23)
  BOTTOM w0.381: U13.1 v2(66.25,6.93) 65.18,6.93 64.5,7.62 56.89,7.62 56.2,6.93 C92.1 ; U12.1 v2(51.01,6.93) C92.1 ; C92.1 U14.1 ; v2(14.73,6.05) J4.1
MLINK_FB: length 16.7
  TOP w0.203: U6.39 42.44,28.5 42.08,28.86 42.08,31.14 42.44,31.5 U6.45 44.73,31.5 44.99,31.76 C66.1 C65.1 47.58,31.76 47.85,31.49 47.85,30.83 48.31,30.36 L6.2 50.54,29.23 50.77,29 51.4,29 51.58,28.83 C67.1
MLINK_LX: length 7.4
  TOP w0.203: L6.1 45.64,34.17 44.48,33 U6.48
P_LED: length 10.6
  TOP w0.381: JS2.1 LED2.A LED3.A 21.47,7.65 21.85,8.03 23.86,8.03 24.24,7.65 LED4.A
P_VDD_SWITCH: length 22.6
  TOP w0.381: JP1.2 53.6,36.04 51.05,36.04 50.62,36.47 JP3.1 49.33,39.17 49.33,46.19 50.32,47.18 50.32,50.43 SH21.2
PIO0_5-ISP_EN: length 1.7
  BOTTOM w0.381: J4.7 R51.2
PIO0_5-ISP_EN-LED_SWD_ACT: length 55.5
  TOP w0.203: v1(24.75,26.44) 26.31,28 U6.88
  L3_INT_1 w0.381: v2(22.74,5.82) 22.26,5.35 16.74,5.35 15.06,7.02 12.84,7.02 12.29,6.47 4.76,6.47 JP12.2
  L4_INT_2 w0.381: v1(24.75,26.44) 24.75,19.64 25.82,18.57 25.82,8.91 v2(22.74,5.82)
  BOTTOM w0.381: R51.1 R48.2 4.93,6.31 JP12.2
PIO0_10-SWO: length 52.5
  TOP w0.203: U6.21 v1(39.81,21.36)
  L3_INT_1 w0.127: J4.6 13.28,2.29 23.92,2.29 24.99,1.23 v1(25.03,1.23) ; v1(39.81,21.36) 38.52,20.06 26.29,20.06 v1(24.02,17.79)
  L4_INT_2 w0.127: v1(24.02,17.79) 24.02,16.89 24.6,16.31 24.6,8.59 22.25,6.23 22.25,4.01 v1(25.03,1.23)
  BOTTOM w0.203: R46.2 J4.6
PIO0_11-SWDCLK: length 49.2
  TOP w0.203: v1(33.78,23.94) 33.78,23.05 34.2,22.63 34.94,22.63 35.81,21.76 U6.13
  L3_INT_1 w0.127: v1(17.33,25.44) 17.8,25.91 20.18,25.91 23.14,22.95 30.92,22.95 32.38,24.41 33.31,24.41 v1(33.78,23.94)
  L4_INT_2 w0.127: J4.4 14.09,4.02 14.09,6.84 16.09,8.84 16.09,12.38 16.76,13.06 16.76,15.23 17.91,16.38 17.91,20.05 17.33,20.62 v1(17.33,25.44)
  BOTTOM w0.203: R53.1 J4.4
PIO0_12-SWDIO: length 46.5
  TOP w0.203: U6.12 35.31,21.39 34.63,22.07 33.57,22.07 32.76,22.87 v1(32.76,23.94)
  L3_INT_1 w0.127: v1(32.76,23.94) 31.39,22.56 22.92,22.56 20.09,25.4 v1(18.35,25.4)
  L4_INT_2 w0.127: J4.2 15.36,4.02 15.36,7.58 16.5,8.72 16.5,12.26 17.07,12.83 17.07,15.03 18.35,16.31 v1(18.35,25.4)
  BOTTOM w0.203: R47.2 J4.2
PO_LED: length 1.3
  TOP w0.254: R25.1 LED3.C
PTD2/TMP1_CH0: length 29.9
  L4_INT_2 w0.127: JP23.2 6.36,9.67 5.06,9.67 4.58,10.15 4.58,18.3 7,20.71 v1(7,30.44)
  BOTTOM w0.203: SH3.1 4.53,31.27 4.89,30.91 6.53,30.91 v1(7,30.44)
PTD3/I2C1_SDA: length 33.3
  L3_INT_1 w0.127: v2(17.33,35.3) 16.86,35.77 14.47,35.77 12.85,34.16 v1(10.22,34.16)
  L4_INT_2 w0.127: v1(10.22,34.16) 10.65,33.73 10.65,33.01 10.44,32.8 9.71,32.8 9.4,32.49 9.4,30.6 8.14,29.34 8.14,18.55 7.11,17.52 7.11,12.99 7.65,12.45 JP24.2
PWM: length 3.3
  BOTTOM w0.203: J2.1 4.53,35.96 SH3.2
RESET: length 1.9
  BOTTOM w0.127: SH1.1 J1.2
RF_50: length 2.2
  TOP w0.417: C3.1 C2.1 L10.2
RF_ANT_1: length 20.5
  TOP w0.417: C97.2 84.1,23.65 86.03,22.75 86.03,22.75 arc(87.94,21.75) 89.62,20.38 ANT10.1
RF_ANT_2: length 20.5
  TOP w0.417: C99.2 84.1,32.35 86.03,33.25 86.03,33.25 arc(87.94,34.25) 89.62,35.62 ANT20.1
RF_GPO_4: length 146.6
  TOP w0.203: J12.4 v1(36.7,5.57) ; v1(62.91,21.47) U1.24
  L3_INT_1 w0.127: v1(73.78,32.83) 72.98,33.63 65.31,33.63 64.45,32.76 56.88,32.76 56.53,33.12 55.95,33.12 55.06,32.23 49.6,32.23 48.41,33.42 42.68,33.42 42.07,32.8 36.21,32.8 35.62,33.4 v1(34.86,33.4) ; v1(62.91,21.47) 63.47,22.04 64.53,22.04 66.1,20.47 66.1,18.54 65.66,18.09 65.66,16.99 66.29,16.36 70.22,16.36 v1(73.02,19.16) ; v1(36.7,5.57) 39.24,5.57 40.14,6.46 43.11,6.46 43.52,6.87 44.24,6.87 44.46,6.65 49.99,6.65 51.58,5.06 56.17,5.06 57.37,6.25 68.83,6.25 69.62,5.47 v1(69.62,4.64)
  L4_INT_2 w0.127: v1(36.7,5.57) 36.7,7.9 34.08,10.53 34.08,16.11 35.21,17.25 35.21,29.99 34.38,30.83 34.38,32.92 v1(34.86,33.4) ; v1(73.02,19.16) 73.04,19.14 73.04,19.11 74.33,17.82 74.33,9.07 72.93,7.67 70.77,7.67 69.62,6.51 v1(69.62,4.64)
  BOTTOM w0.203: SH24.3 v1(73.78,32.83) ; SH9.1 v1(73.02,19.16)
RF_GPO_5: length 135.5
  TOP w0.203: U1.25 64.12,23 64.43,22.69 v1(64.43,20.67)
  L3_INT_1 w0.127: v1(64.43,20.67) 64.11,20.35 55.59,20.35 53.34,22.61 46.5,22.61 45.33,21.43 41.16,21.43 v1(40.62,21.97) ; v1(70.73,30.79) 67.94,30.79 67.48,31.25 65.12,31.25 62.62,28.76 50.08,28.76 47.04,25.71 26.04,25.71 25.3,24.97 v1(22.65,24.97) ; v1(22.65,8.7) 24.49,8.7 28.56,4.62 37.61,4.62 J12.5
  L4_INT_2 w0.127: v1(22.65,8.7) v1(22.65,24.97) ; J12.5 38.7,13.61 38.99,13.9 38.99,19.16 40.62,20.8 v1(40.62,21.97)
  BOTTOM w0.203: v1(70.73,30.79) SH24.1 R115.2
RF_GPO_6: length 67.5
  TOP w0.203: v1(65.24,20.1) 64.89,20.46 64.89,22.86 64.24,23.5 U1.26
  L3_INT_1 w0.127: v1(65.24,20.1) 55.46,20.1 53.23,22.33 47.78,22.33 46.49,21.03 40.77,21.03 40.75,21.01 40.67,21.01 39.06,19.4 26.45,19.4 23.9,16.86 20.89,16.86 19.58,15.54 v1(12,15.54)
  BOTTOM w0.203: JP24.1 10.98,11.17 12,12.19 v1(12,15.54)
RST_TGTMCU_B: length 96.2
  TOP w0.203: U1.23 62.41,20.97 63.85,19.53 v1(64.43,19.53) ; SW1.2 66.53,3.8 66.95,4.23 66.95,9.58 67.81,10.44 JS3.1
  L3_INT_1 w0.127: v1(51.42,19.61) 53.45,17.58 56.75,17.58 57.4,16.93 61.83,16.93 v1(64.43,19.53) ; v1(9.2,17.09) 9.2,16.08 10.25,15.03 21.39,15.03 22.03,15.67 35.02,15.67 35.57,15.11 49.44,15.11 49.99,15.67 52.45,15.67 JP25.2
  L4_INT_2 w0.127: JP25.2 51.42,16.7 v1(51.42,19.61)
  BOTTOM w0.127: v1(9.2,17.09) SH1.2
  BOTTOM w0.203: JS3.1 67.56,10.44 63.25,14.74 63.25,17.81 64.43,18.99 v1(64.43,19.53)
RST_U11: length 7.5
  L4_INT_2 w0.127: JP25.1 50.23,15.89 50.23,17.47 50.78,18.02 v1(50.78,19.61)
  BOTTOM w0.127: U11.8 51.48,18.91 51.03,18.91 50.78,19.15 v1(50.78,19.61)
SCK: length 4.2
  TOP w0.203: TP8.1 v2(67.94,45.08)
  BOTTOM w0.203: v2(67.94,45.08) R10.2
SI: length 3.2
  TOP w0.203: TP10.1 v2(67.94,43.81)
SO: length 11.8
  TOP w0.203: v2(60.68,46.35) 63.71,46.35 66,48.64 69.28,48.64 70.3,47.62 TP13.1
SPI_PSC0: length 1.9
  BOTTOM w0.127: SH4.1 J1.3
SPI_SCK: length 1.9
  BOTTOM w0.127: SH6.1 J1.4
SPI_SIN: length 1.9
  BOTTOM w0.127: SH8.1 J1.5
SPI_SOUT: length 1.9
  BOTTOM w0.127: SH10.1 J1.6
SWD_CLK: length 14.1
  TOP w0.203: R66.1 v1(52.05,16.98) ; U1.9 v1(55.42,24.5)
  L4_INT_2 w0.127: v1(55.42,24.5) 56.04,24.5 56.35,24.19 56.35,23.01 55.95,22.6 55.95,21.42 54.97,20.44 53.51,20.44 53.09,20.02 53.09,18.02 v1(52.05,16.98)
  BOTTOM w0.203: U11.4 52.61,17.08 52.5,16.98 v1(52.05,16.98)
SWD_DIO: length 14.2
  TOP w0.203: U1.8 v1(55.88,25)
  L4_INT_2 w0.127: v1(55.88,25) 56.23,25 56.66,24.58 56.66,22.58 56.99,22.25 56.99,18.87 55.53,17.41 55.53,16.2 v1(55.1,15.77)
  BOTTOM w0.203: v1(55.1,15.77) 55.39,16.06 55.39,17.14 54.83,17.71 U11.16
SWITCH_WAKEUP_B: length 19.8
  TOP w0.203: U1.5 v1(55.88,26.5)
  L3_INT_1 w0.127: v1(56.31,32.64) 56.5,32.45 65.38,32.45 65.57,32.64 TP4.1
  BOTTOM w0.127: v1(55.88,26.5) 56.31,26.93 v1(56.31,32.64)
SWO/BOOT_CFG: length 21.1
  TOP w0.203: SH20.1 49.82,10.76 50.36,11.3 51.54,11.3 51.89,11.65 v1(51.89,12.52) ; U1.10 55.34,24 54.35,23.01 54.35,20.39 v1(53.81,19.85)
  L4_INT_2 w0.127: v1(53.81,19.85) 53.81,16.48 54.56,15.73 54.56,13.24 53.85,12.52 v1(51.89,12.52)
  BOTTOM w0.203: U11.12 v1(53.81,19.85)
TMP1_CH0: length 91.7
  TOP w0.203: v2(63.55,31.19) 62.91,30.55 U1.37
  L3_INT_1 w0.127: JS14.1 30.68,9.29 30.11,9.86 30.11,11.1 29.9,11.31 25.97,11.31 25.55,10.89 23.74,10.89 20.97,8.12 16.89,8.12 14.48,10.54 10.46,10.54 9.65,9.72 JP23.1 ; v2(63.55,31.19) 63.41,31.06 63.41,30.1 62.37,29.06 49.89,29.06 46.85,26.02 29.43,26.02 28.45,27 v1(26.64,27)
  L4_INT_2 w0.127: JS14.1 28.4,8.33 27.02,9.71 27.02,17 27.22,17.2 27.22,26.42 v1(26.64,27)
TMP1_CH5: length 65.7
  TOP w0.203: U1.44 v1(59.41,30.05)
  L3_INT_1 w0.127: v1(59.41,30.05) 58.94,30.52 50.04,30.52 47.74,28.22 42.74,28.22 42.47,28.49 27.49,28.49 24.75,25.76 21.56,25.76 20.52,26.79 v1(18.98,26.79)
  L4_INT_2 w0.127: v2(17.61,6.28) 16.93,6.96 16.93,12.13 17.37,12.57 17.37,14.87 18.98,16.47 v1(18.98,26.79)
UART0_RX: length 89.7
  TOP w0.198: U1.11 v1(55.88,23.5)
  L3_INT_1 w0.143: JS10.3 52.17,42.35 53.73,42.35 54.69,43.31 54.69,44.8 54.09,45.4 49.99,45.4 49.27,44.68 43.6,44.68 40.89,41.96 31.67,41.96 30.52,40.81 29.14,40.81 26.82,38.49 26.51,38.49 7.67,38.49 6.94,37.76 6.94,32.92 JS5.2
  L4_INT_2 w0.143: v1(55.88,23.5) 55.7,23.65 55.5,23.63 55.4,23.7 55.27,23.84 53.64,23.84 52.79,24.69 52.79,26.27 51.41,27.65 51.41,36.08 51.8,36.47 51.8,38.6 50.79,39.61 49.73,39.61 49.59,39.75 49.59,41.46 50.62,42.49 50.82,42.49 50.97,42.35 JS10.3
UART0_TX: length 78.2
  TOP w0.198: U1.12 v1(55.47,23)
  L3_INT_1 w0.143: JS6.2 7.3,35.05 7.3,37.62 7.82,38.13 26.66,38.13 26.97,38.13 29.29,40.45 30.66,40.45 31.82,41.61 41.04,41.61 43.75,44.32 JS11.3
  L4_INT_2 w0.143: v1(55.47,23) 55.29,23.15 55.27,23.35 55.16,23.44 55.12,23.48 53.49,23.48 52.43,24.54 52.43,26.12 51.05,27.5 51.05,36.23 51.44,36.62 51.44,38.45 50.64,39.25 49.58,39.25 49.23,39.6 49.23,41.61 50.53,42.91 50.82,42.91 50.97,43.05 JS11.3
UART1_RX: length 50.8
  L3_INT_1 w0.127: JS10.1 56.06,41.14 57.08,42.16 57.08,45.35 56.11,46.32 49.3,46.32 48.6,45.63 42.98,45.63 40.39,43.03 31.1,43.03 29.87,41.8 28.72,41.8 27.3,40.38 v1(25.08,40.38)
  L4_INT_2 w0.127: JP27.1 22.58,32.07 22.38,32.26 22.38,38.2 23.06,38.87 24.37,38.87 25.08,39.58 v1(25.08,40.38)
UART1_RX/CAN1_RX: length 44.4
  TOP w0.198: U1.39 v1(61.91,30.04)
  L3_INT_1 w0.143: v1(61.91,30.04) 61.57,30.04 60.98,30.64 60.98,31.32 60.56,31.73 59.09,31.73 58.91,31.55 58.8,31.55 58.79,31.55 56.94,31.55 56.93,31.55 48.97,31.55 48.11,32.41 43.06,32.41 41.91,31.26 41.9,31.26 41.82,31.18 41.68,31.18 41.53,31.18 41.52,31.18 32.2,31.18 32.2,31.18 32.05,31.18 31.9,31.18 31.82,31.26 31.82,31.26 31.34,31.73 26.35,31.73 24.68,30.07 JP27.2
  BOTTOM w0.198: v1(61.91,30.04) 61.91,31.17 61.64,31.44 C163.1
UART1_TX: length 46.8
  L3_INT_1 w0.127: v1(24.42,40.38) 24.84,39.96 27.36,39.96 28.86,41.47 30,41.47 31.24,42.7 40.53,42.7 43.12,45.29 48.74,45.29 49.44,45.98 55.68,45.98 56.05,45.62 JS11.1
  L4_INT_2 w0.127: JP28.1 21.86,32.07 22.05,32.26 22.05,38.33 22.92,39.2 24.1,39.2 24.4,39.5 24.4,40.37 v1(24.42,40.38)
UART1_TX/CAN1_TX: length 46.6
  TOP w0.198: U1.40 v1(61.41,30.87)
  L3_INT_1 w0.143: JP28.2 21.93,31.11 25.22,31.11 26.2,32.09 31.49,32.09 32.04,31.54 41.68,31.54 42.83,32.69 42.83,32.69 42.91,32.77 43.06,32.77 43.21,32.77 43.21,32.76 48.26,32.76 49.12,31.91 56.94,31.91 56.94,31.91 57.08,31.91 57.09,31.91 58.76,31.91 58.94,32.09 60.71,32.09 61.23,31.57 61.24,31.57 61.41,31.4 v1(61.41,30.87)
  BOTTOM w0.198: v1(61.41,30.87) 60.76,31.52 C164.1
UART_RX: length 6.4
  TOP w0.203: JS5.1 6.19,35.28 6.53,35.62 9.27,35.62 J2.3
UART_TX: length 8.4
  TOP w0.203: JS6.1 9.19,32.16 9.42,32.39 9.42,34.57 10.3,35.45 11.64,35.45 J2.4
USB1_VBUS: length 5.2
  TOP w0.203: R41.1 R37.2 46.22,27.5 45.72,27 U6.36
V_BRD: length 168.3
  TOP w0.254: U17.6 17.21,40.47 v2(17.72,40.99) ; U20.6 v2(17.72,43.52) ; U24.6 v2(16.34,25.79) ; v2(13.81,25.79) 13.81,25.84 13.29,26.36 U22.6
  TOP w0.381: SH19.1 40.92,52.93 41.63,53.64 JP2.4
  L3_INT_1 w0.381: v2(66.5,53.21) 50.42,53.21 49.84,52.64 45.23,52.64 JP2.4 ; v1(20.89,19.17) 20.89,21.53 19.09,23.33 16.86,23.33 16.34,23.85 v2(16.34,25.79) v2(13.81,25.79)
  L4_INT_2 w0.381: v2(16.34,25.79) 16.34,26.44 15.67,27.11 15.67,30.47 16.7,31.5 16.7,35.81 17.05,36.17 17.05,37.44 17.05,37.44 17.05,40.31 v2(17.72,40.99) v2(17.72,43.52) 16.89,44.35 16.89,48.19 18.55,49.85 20.55,49.85 22.8,52.1 22.8,53.77 23.93,54.9 42.97,54.9 JP2.4 ; v2(48.63,21.22) 48.63,22.2 47.78,23.06 47.78,41.18 49.18,42.57 49.18,44.7 51.97,47.49 JS1.2 ; JS2.2 20.2,12.52 19.57,13.15 19.57,15.39 20.89,16.71 v1(20.89,19.17)
  BOTTOM w0.381: R205.1 R206.1 52.74,23.21 52.21,22.68 49.08,22.68 48.63,22.24 v2(48.63,21.22) ; v2(66.5,53.21) 63.13,49.84 54.44,49.84 54.05,49.44 JS1.2
  BOTTOM w0.508: SH12.2 C42.1 v1(20.89,19.17)
V_LDO_OUT: length 9.7
  TOP w0.254: C24.1 36.86,53.78 ; C24.1 35.94,52.55 ; C24.1 36.86,51.32 ; C24.1 37.77,52.55 ; D1.A 39.15,53.21 ; D1.A 39.15,51.89 ; D1.A 38.32,52.55 ; U4.5 34.61,53.24 ; U4.5 35.42,52.67 ; U4.5 33.79,52.67
  BOTTOM w0.381: U4.5 v1(35.62,52.67)
V_SEC: length 33.3
  L3_INT_1 w0.381: JP10.2 59.82,38.74 49.51,38.74 48.94,38.16 v1(48.94,37.49)
  L4_INT_2 w0.381: v1(48.94,37.49) 48.94,23.55 JP4.1
  BOTTOM w0.305: JP6.1 JP10.2
VOUT_MLINK: length 3.8
  TOP w0.381: R34.1 v2(17.3,19.21)
  BOTTOM w0.381: v2(15.27,19.21) v2(17.3,19.21)
VOUT_SWITCH: length 16.9
  TOP w0.254: v2(53.61,25.5) C28.1 U1.7
  L4_INT_2 w0.381: v2(53.61,25.5) 53.61,26.66 52.45,27.81 52.45,35.73 54.61,37.88 JP3.3
VREF_MCULINK: length 35.7
  TOP w0.254: v1(32.45,40.84) 34.21,40.84 35.18,39.87 R42.2 ; U7.1 R33.2 38.45,15.54 38.58,15.66 C70.1 C71.1 38.58,18.41 37.81,19.18 U6.17 v1(37.81,21.38)
  L4_INT_2 w0.254: v1(32.45,40.84) 34.66,38.63 34.66,36.68 37.24,34.11 37.24,33.59 38.35,32.48 38.35,22.58 37.81,22.04 v1(37.81,21.38)
VREF_OUT: length 21.8
  TOP w0.203: U1.30 63.98,25.5 64.12,25.36 64.77,25.36 v1(65.77,24.36)
  BOTTOM w0.381: v1(65.77,24.36) 65.92,24.52 65.92,25.06 65.48,25.5 C15.1 63.34,22.51 63.72,22.13 64.21,22.13 65.32,21.03 68.15,21.03 71,18.18 71,16.7 TP2.1
WP: length 1
  BOTTOM w0.203: R19.2 v2(60.68,45.08)
WUU0_P8: length 32.8
  TOP w0.203: SW2.2 R9.2 v2(57.91,52.2) TP9.1 ; v2(62.66,31.19) 62.41,30.94 U1.38
  L3_INT_1 w0.127: v1(62.66,52.2) v2(57.91,52.2)
  L4_INT_2 w0.127: v2(62.66,31.19) 62.66,33.54 62.98,33.86 62.98,36.05 61.58,37.45 61.58,51.11 62.66,52.2 v1(62.66,52.2)
WUU0_P12/NMI_B: length 146.7
  TOP w0.203: U1.45 58.91,34.56 60.4,36.05 v1(60.41,36.05) ; TP12.1 v2(67.64,52.2) R17.2 SW3.2
  L3_INT_1 w0.127: v1(10.22,33.27) 12.49,33.27 13.75,34.53 26.15,34.53 26.7,35.08 52.36,35.08 54.1,36.82 59.63,36.82 v1(60.41,36.05) ; v1(11.82,9.78) 13.78,9.78 16.24,7.31 25.15,7.31 28.13,4.32 33.91,4.32 J12.3 ; v2(67.64,52.2) 66.37,50.93 v1(59.16,50.93)
  L4_INT_2 w0.127: v1(60.41,36.05) 59.97,36.48 59.97,39.7 59.43,40.24 59.43,46.61 59.16,46.88 v1(59.16,50.93) ; v1(11.82,9.78) 7.09,9.78 6.46,10.41 6.46,12.64 6.73,12.91 6.73,18.14 7.76,19.17 7.76,29.48 9.01,30.73 9.01,32.64 9.65,33.27 v1(10.22,33.27)
  BOTTOM w0.203: SH5.1 9.79,35.3 9.54,35.05 9.54,33.47 9.74,33.27 v1(10.22,33.27)
XTAL32K: length 6.1
  TOP w0.127: R30.1 66.13,20.45 66.13,20.85 65.62,21.36 65.62,23.07 64.88,23.81 64.38,23.81 64.19,24 U1.27
XTAL32K_PTD4: length 3.1
  TOP w0.127: C49.1 Y2.1 68.52,19.52 68.2,19.84 R30.2
XTAL_OUT: length 22.6
  TOP w0.203: U1.31 63.94,26 64.23,25.71 64.88,25.71 65.71,24.88 66.45,24.88 v1(66.69,24.64)
  L4_INT_2 w0.127: TP22.1 70.77,12.2 70.77,15.5 71.17,15.9 71.17,21.43 70.72,21.89 67.32,21.89 66.73,22.48 66.73,24.64 v1(66.69,24.64)
XTAL_RF: length 6.6
  TOP w0.127: U1.32 64.3,26.5 v1(64.41,26.39)
  L3_INT_1 w0.127: v1(64.41,26.39) 64.54,26.39 65.06,25.87 66.86,25.87 67.46,25.27 67.46,23.6 v2(67.89,23.17)
N22669333: length 4.6
  BOTTOM w0.203: R63.1 59.28,6.41 59.68,6.81 61.36,6.81 61.72,6.45 61.72,5.36 U10.7
N22669352: length 4.2
  BOTTOM w0.203: U10.6 61.22,6.2 61.08,6.34 60.21,6.34 59.98,6.12 59.98,4.93 59.69,4.64 R64.1
N22669391: length 7
  TOP w0.203: R65.1 v1(50.78,16.98)
  L3_INT_1 w0.127: v1(50.78,16.98) 51.52,16.24 52.84,16.24 53.29,16.69 v1(54.74,16.69)
  BOTTOM w0.203: U11.1 53.81,17.01 54.14,16.69 v1(54.74,16.69)
N22669418: length 10.5
  TOP w0.203: v1(52.05,19.61) R67.1 R65.2 50.08,18.88 JP17.1
  BOTTOM w0.203: U11.5 48.91,17.71 JP17.1 ; v1(52.05,19.61) 52.41,19.61 52.61,19.4 U11.9 52.61,18.44 52.76,18.29 53.18,18.29 53.41,18.06 U11.2
N22669601: length 1.1
  BOTTOM w0.203: R70.1 U12.5
N22669605: length 2.3
  BOTTOM w0.203: U12.4 52.31,2.84 R69.1 R68.2
N22669808: length 2.3
  BOTTOM w0.203: R72.2 R73.1 67.55,2.84 U13.4
N22669908: length 2.4
  TOP w0.381: D12.C JP18.3
N22670160: length 2.3
  BOTTOM w0.203: U14.4 56.88,2.84 R78.1 R76.2
N22670341: length 1.3
  TOP w0.254: U15.4 R83.1
N22888978: length 2.2
  TOP w0.203: R71.1 46.91,16.87 JP17.2
N22954457: length 2.2
  TOP w0.203: U16.3 37.26,9.13 36.88,8.75 R84.1
N22954468: length 5.2
  TOP w0.203: U16.4 37.76,9.13 38.15,8.75 v2(38.15,8.18)
  L3_INT_1 w0.127: v2(38.15,8.18) v2(41.19,8.18)
N22954480: length 5.7
  TOP w0.203: v2(41.17,10.21) 41.17,11.03 40.52,11.68 U16.9
  BOTTOM w0.127: v2(41.17,10.21) 42.28,10.21 43.1,11.02 Q3.3
N23559922: length 5.6
  TOP w0.254: U6.58 38.31,37.06 39.31,38.06 R38.2 38.55,39.11 R42.1
N23802482: length 1.3
  TOP w0.203: R50.2 D7.A
N23938720: length 53.4
  TOP w0.203: R84.2 35.87,7.51 36.7,6.68 42.02,6.68 43.09,7.75 v1(43.09,9.93)
  L3_INT_1 w0.127: JS10.2 52.5,40.14 43.64,40.14 v1(41.29,37.79)
  L4_INT_2 w0.127: v1(41.29,37.79) 40.87,37.37 40.87,36.34 43.09,34.12 v1(43.09,9.93)
N23938761: length 51.9
  TOP w0.203: R85.2 39.91,7.43 41.41,7.43 v1(42.16,8.18)
  L3_INT_1 w0.127: JS11.2 52.24,43.05 50.22,43.05 49.21,42.03 v1(43.16,42.03)
  L4_INT_2 w0.127: v1(42.16,8.18) 42.63,8.65 42.63,33.94 40.22,36.34 40.22,40.31 41.94,42.03 v1(43.16,42.03)
N24355935: length 1.2
  TOP w0.127: R1.2 60.56,19.48 C8.1
N24374306: length 2.5
  BOTTOM w0.254: JP7.2 65.44,15.48 65.18,15.74 SH22.1
N24374396: length 2.3
  TOP w0.381: JP6.2 SH23.1
N24441947: length 9.3
  TOP w0.203: U2.6 v2(75.05,26.13)
  BOTTOM w0.203: v2(75.05,26.13) C20.1 75.05,24.21 73.91,23.07 73.91,20.69 v2(73.91,20.68) SH9.2
N24444926: length 25.4
  TOP w0.417: J8.1 76.77,30.01
N24446994: length 1.2
  TOP w0.203: R24.1 LED1.C
N24467715: length 19.9
  TOP w0.381: J3.SH1 J3.SH3 J3.SH4 J3.SH2
  BOTTOM w0.381: R114.2 C155.2 J3.SH2
N24516334: length 5.9
  TOP w0.203: U2.4 75.05,30.18 74.43,30.79 v1(72.26,30.79)
  BOTTOM w0.203: SH24.2 v1(72.26,30.79)
N24687861: length 5.1
  BOTTOM w0.381: v2(31.31,49.67) 33.21,49.67 33.59,50.04 R202.1 R201.1 R200.2
N24687954: length 1
  BOTTOM w0.381: R202.2 R203.1
N24732897: length 25.4
  TOP w0.417: 76.77,25.99 J7.1
N24840090: length 1.2
  TOP w0.203: U17.4 17.21,39.47 v2(17.72,38.96)
N24840097: length 4.3
  TOP w0.203: R45.2 10.25,39.74 10.71,40.2 C110.2 10.71,41.8 10.43,42.08 10.43,42.08 10.23,42.28 R99.1
N24840123: length 1.2
  TOP w0.203: U20.4 17.21,42.52 R100.1
N24840158: length 1.2
  TOP w0.203: R117.1 12.29,26.31 U22.4
N24840165: length 4.1
  TOP w0.203: R119.2 14.18,30.53 14.39,30.73 C160.2 14.39,32.36 14.18,32.56 R118.1
N24840191: length 1.2
  TOP w0.203: R120.1 15.34,26.31 U24.4

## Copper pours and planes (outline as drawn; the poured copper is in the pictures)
1V8_DCDC on TOP: 62.14,17.05 62.14,15.76 61.97,15.58 61.22,15.58 58.14,12.5 55.41,12.5 54.93,12.98 54.93,15.01 55.24,15.31 58.44,15.31 58.79,15.67 58.79,16.34 59.09,16.63 59.88,16.63 59.88,17.05
GND on TOP: 0.51,55.49 82.51,55.49 109.49,28.51 109.49,27.49 82.51,0.51 0.51,0.51 ; 15 cut-outs
GND on BOTTOM: 0.51,55.49 82.51,55.49 109.49,28.51 109.49,27.49 82.51,0.51 0.51,0.51 ; 4 cut-outs
GND on L2_GND_1: 0.51,55.49 82.51,55.49 109.49,28.51 109.49,27.49 82.51,0.51 0.51,0.51 ; 1 cut-out
GND on L4_INT_2: 0.51,55.49 82.51,55.49 109.49,28.51 109.49,27.49 82.51,0.51 0.51,0.51 ; 17 cut-outs
GND on L5_GND_2: 0.51,55.49 82.51,55.49 109.49,28.51 109.49,27.49 82.51,0.51 0.51,0.51
P3V3_BATT on TOP: 37.18,45.62 39.29,45.62 39.54,45.36 39.54,43.84 39.26,43.56 37.14,43.56 36.91,43.79 36.91,45.35
P3V3_BATT on BOTTOM: 34.37,46.53 39.3,46.53 39.63,46.2 39.63,38.15 39.2,37.72 34.48,37.72 33.84,38.35 33.84,46
P5V_CAN on TOP (solid shape): outline of 90 points within 20.19,40.85 29.43,45.6
P12V on BOTTOM: 22.78,48.1 22.78,45.8 22.48,45.5 20.71,45.5 20.43,45.77 20.43,47.18 19.02,48.59 11.87,48.59 11.08,47.8 11.08,44.46 10.63,44 9.36,44 8.88,44.48 8.88,46.81 8.27,47.42 1.43,47.42 0.75,48.1 0.75,49.41 1.41,50.07 19.93,50.07 21.34,48.66 22.22,48.66
VBAT_DCDC/VBAT_PMU on TOP: 41.99,42.87 39.99,42.87 39.86,42.75 39.86,41.96 40.04,41.78 41.36,41.78 41.88,41.26 41.88,37.21 41.67,37 41.67,33.86 42.17,33.36 44.31,33.36 44.31,33.64 43.59,33.64 43.53,33.7 43.53,33.8 43.59,33.86 44.31,33.86 44.31,34.14 43.59,34.14 43.4,34.32 43.4,41.46
VCC_IF_LINK on BOTTOM: 62.08,4.75 62.74,4.75 63.02,5.02 63.97,5.02 64.18,5.22 64.18,5.73 63.8,6.11 62.51,6.11 62.34,5.96 62.08,5.96
(no net) on TOP: 20.48,44.19 20.19,43.9 20.19,42.36 20.34,42.21 24.86,42.21 26.22,40.85 29.16,40.85 29.43,41.12 29.43,45.2 29.03,45.6 26.28,45.6 24.86,44.19
(no net) on L3_INT_1: 0.51,55.49 82.51,55.49 109.49,28.51 109.49,27.49 82.51,0.51 0.51,0.51 ; 34 cut-outs
DCDC_LX on TOP (solid shape): 61.56,20.25 61.56,19.19 61.74,19.01 62,19.01 62,17.7 60.49,17.7 60.49,19.02 60.82,19.02 60.96,19.17 60.96,19.88 60.75,20.09 60.75,20.75 60.85,20.86 60.95,20.86
MCU_LINK_3V3 on TOP: 27.31,22.14 28.76,22.14 28.76,19.66 27.59,18.48 27.32,18.48 27.07,18.23 27.07,17.57 26.94,17.44 26.35,17.44 26.2,17.59 26.2,18.18 25.59,18.79 25.59,19.27 24.96,19.9 20.72,19.9 20.37,20.25 20.37,21.16 20.56,21.34 25.64,21.34 25.74,21.24 25.74,20.8 26.11,20.44 27.02,20.44 27.31,20.73
